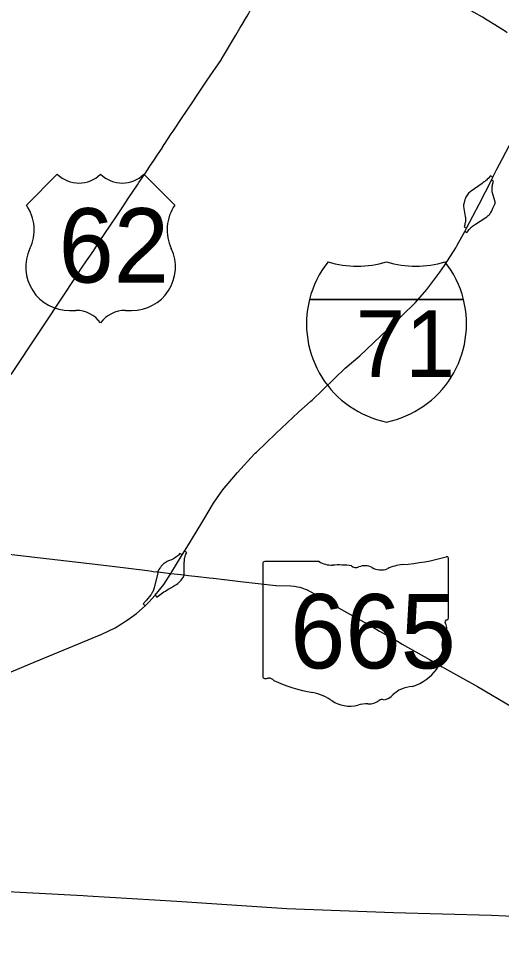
# Model space of a CAD drawing. Extents: x -7.1 to 34, y 0 to 22.
# Drawn here: x 4.231 to 5.069, y 14.423 to 16.034 of the extents above; entities that cross this region are included whole.
import ezdxf

# ---------------------------------------------------------------- set-up
doc = ezdxf.new("R2010")
doc.units = 0
for name, color, linetype in [('GM_X_County', 7, 'Continuous'), ('GM_X_Interchange_Ramps', 7, 'Continuous'), ('GM_X_Interstate_Route', 7, 'Continuous'), ('GM_X_Interstate_Shield', 7, 'Continuous'), ('GM_X_State_Route', 7, 'Continuous'), ('GM_X_State_Shield', 7, 'Continuous'), ('GM_X_US_Route', 7, 'Continuous'), ('GM_X_US_Shield', 7, 'Continuous')]:
    doc.layers.add(name, color=color, linetype=linetype)

msp = doc.modelspace()

# ---------------------------------------------------------------- linework, layer by layer
at = {"layer": 'GM_X_County'}
msp.add_lwpolyline([(6.4816, 14.3958), (6.2397, 14.409), (6.239, 14.4092), (5.9929, 14.4242), (5.7569, 14.4401), (5.6674, 14.444), (5.5093, 14.4541), (5.4881, 14.4554), (5.313, 14.4679), (5.276, 14.4703), (5.0902, 14.4781), (5.0763, 14.4786), (5.0514, 14.4796), (4.8814, 14.4845), (4.6962, 14.4912), (4.5056, 14.5037), (4.3509, 14.5133), (4.3432, 14.5137), (4.1028, 14.5264)], dxfattribs=at)
at = {"layer": 'GM_X_Interchange_Ramps'}
for points in [[(5.0539, 15.7589), (5.0496, 15.7612), (5.0454, 15.7566), (5.0441, 15.7553), (5.0426, 15.7538), (5.0415, 15.7528), (5.04, 15.7515), (5.0388, 15.7506), (5.0372, 15.7495), (5.035, 15.748), (5.0159, 15.7346), (5.0145, 15.7336), (5.0131, 15.7323), (5.0117, 15.7309), (5.0102, 15.7292), (5.009, 15.7276), (5.008, 15.7261), (5.007, 15.7244), (5.0061, 15.7227), (5.005, 15.7204), (5.0032, 15.7129), (5.003, 15.7108)], [(5.0576, 15.7139), (5.0575, 15.7158), (5.0528, 15.7336), (5.0526, 15.7354), (5.0525, 15.7372), (5.0524, 15.7389), (5.0525, 15.7407), (5.0526, 15.7426), (5.0529, 15.7444), (5.0532, 15.7462), (5.0536, 15.7481), (5.0548, 15.7521), (5.0513, 15.7539)], [(5.003, 15.7108), (5.0029, 15.7082), (5.0058, 15.6909), (5.0061, 15.6892), (5.0062, 15.6873), (5.0063, 15.6854), (5.0062, 15.6836), (5.006, 15.6816), (5.0058, 15.6799), (5.0054, 15.6784), (5.0049, 15.6765), (5.0037, 15.6726), (5.0081, 15.6702)], [(5.0052, 15.6648), (5.0085, 15.6631), (5.0128, 15.6682), (5.0138, 15.6693), (5.0147, 15.6703), (5.0158, 15.6714), (5.0169, 15.6723), (5.0186, 15.6737), (5.02, 15.6748), (5.0216, 15.676), (5.0237, 15.6773), (5.0399, 15.688), (5.0416, 15.6891), (5.0431, 15.6901), (5.0445, 15.6913), (5.0458, 15.6924), (5.0472, 15.6938), (5.0482, 15.695), (5.0493, 15.6964), (5.0503, 15.6978), (5.0512, 15.6992), (5.052, 15.7007), (5.0527, 15.7021), (5.0533, 15.7034), (5.0539, 15.7049), (5.0543, 15.706), (5.0547, 15.7073), (5.0571, 15.7122), (5.0576, 15.7139)], [(4.5184, 15.07), (4.5184, 15.0721), (4.5186, 15.0917), (4.5187, 15.0938), (4.5188, 15.0954), (4.519, 15.0968), (4.5192, 15.0985), (4.5195, 15.0998), (4.5199, 15.1012), (4.5203, 15.1026), (4.5208, 15.104), (4.5213, 15.1054), (4.5228, 15.1085), (4.5189, 15.1108)], [(4.5151, 15.1045), (4.5111, 15.1069), (4.5086, 15.1042), (4.5072, 15.1029), (4.5056, 15.1015), (4.5038, 15.1002), (4.5018, 15.0988), (4.5001, 15.0978), (4.4984, 15.0969), (4.4966, 15.0961), (4.4947, 15.0954), (4.4929, 15.0948), (4.4909, 15.094), (4.4891, 15.0932), (4.4871, 15.092), (4.4851, 15.0908), (4.4833, 15.0894), (4.4815, 15.0878), (4.4801, 15.0863), (4.4787, 15.0847), (4.4771, 15.0826), (4.476, 15.0813), (4.4746, 15.0792), (4.4733, 15.0769), (4.4727, 15.0748)], [(4.4727, 15.0748), (4.4726, 15.0734), (4.4664, 15.0471), (4.4659, 15.0455), (4.4654, 15.044), (4.4647, 15.0424), (4.4639, 15.0406), (4.4631, 15.0392), (4.4625, 15.0381), (4.4619, 15.0371), (4.4611, 15.036), (4.4604, 15.035), (4.4531, 15.0259), (4.4471, 15.0198), (4.4506, 15.0163)], [(4.468, 15.0344), (4.4712, 15.0313), (4.4737, 15.0332), (4.4759, 15.0349), (4.4785, 15.0368), (4.4808, 15.0385), (4.4832, 15.0401), (4.4858, 15.0418), (4.4889, 15.0438), (4.4916, 15.0455), (4.494, 15.0468), (4.4963, 15.0481), (4.5016, 15.0513), (4.5049, 15.0533), (4.5071, 15.0549), (4.5088, 15.0563), (4.5105, 15.0579), (4.5119, 15.0594), (4.5131, 15.0607), (4.5141, 15.0621), (4.5162, 15.0649), (4.5182, 15.0686), (4.5184, 15.07)]]:
    msp.add_lwpolyline(points, dxfattribs=at)
at = {"layer": 'GM_X_Interstate_Route'}
for points in [[(5.0439, 16.0309), (5.0356, 16.0359), (5.0066, 16.052), (4.9932, 16.0577), (4.9706, 16.0673), (4.9492, 16.0752), (4.9186, 16.0839), (4.8566, 16.1006), (4.8408, 16.1047), (4.7979, 16.1157), (4.773, 16.1221), (4.7497, 16.1282), (4.7392, 16.1309), (4.71, 16.1382), (4.6914, 16.1431)], [(5.0785, 16.0089), (5.0754, 16.011), (5.0574, 16.0229), (5.0439, 16.0309)], [(5.0609, 15.7724), (5.0655, 15.7812), (5.0815, 15.8118), (5.0979, 15.8401), (5.1079, 15.8562)], [(5.0551, 15.7611), (5.0609, 15.7724)], [(5.03, 15.7121), (5.03, 15.7121), (5.0513, 15.7539), (5.0539, 15.7589), (5.0551, 15.7611)], [(4.992, 15.6412), (5.0052, 15.6648), (5.0081, 15.6702), (5.03, 15.7121)], [(4.9315, 15.5555), (4.9392, 15.5644), (4.9619, 15.594), (4.97, 15.6056), (4.9893, 15.6366), (4.992, 15.6412)], [(4.8697, 15.4936), (4.88, 15.5032), (4.8971, 15.5195), (4.919, 15.541), (4.9315, 15.5555)], [(4.7382, 15.3705), (4.7401, 15.3722), (4.7977, 15.4277), (4.823, 15.4492), (4.859, 15.4835), (4.8697, 15.4936)], [(4.6404, 15.2792), (4.6415, 15.2804), (4.6435, 15.2826), (4.6776, 15.3146), (4.7168, 15.3516), (4.7382, 15.3705), (4.7382, 15.3705)], [(4.5524, 15.1659), (4.5692, 15.1939), (4.585, 15.2167), (4.611, 15.2473), (4.6404, 15.2792)], [(4.5227, 15.1172), (4.5488, 15.1599), (4.5524, 15.1659)], [(4.4954, 15.0722), (4.5151, 15.1045), (4.5189, 15.1108), (4.5227, 15.1172)], [(4.4273, 14.997), (4.4356, 15.0031), (4.4506, 15.0163), (4.4569, 15.0225), (4.468, 15.0344), (4.4829, 15.0533), (4.4954, 15.0722)], [(4.1211, 14.8623), (4.1234, 14.8633), (4.1817, 14.887), (4.2584, 14.9184), (4.3181, 14.9432), (4.3753, 14.9669), (4.3984, 14.9783), (4.4099, 14.985), (4.4149, 14.9883)], [(4.4149, 14.9883), (4.4214, 14.9926), (4.4273, 14.997)]]:
    msp.add_lwpolyline(points, dxfattribs=at)
at = {"layer": 'GM_X_Interstate_Shield'}
for p, q in [((4.7357, 15.5471), (5.0028, 15.5471)), ((5.0028, 15.5471), (4.7357, 15.5471)), ((5.0028, 15.5471), (4.7357, 15.5471))]:
    msp.add_line(p, q, dxfattribs=at)
for centre, start, end in [((4.904, 15.5046), 141.669, 165.8066), ((4.8186, 15.7781), 253.0091, 286.9909), ((4.92, 15.7781), 253.0091, 286.9909), ((4.8346, 15.5046), 14.1934, 38.331), ((4.904, 15.5046), 165.8066, 258.463), ((4.8346, 15.5046), 281.537, 14.1934)]:
    msp.add_arc(centre, 0.1735, start, end, dxfattribs=at)
at = {"layer": 'GM_X_State_Route'}
for points in [[(4.128, 15.1159), (4.1302, 15.1156), (4.2441, 15.1024), (4.269, 15.0995), (4.3292, 15.0924), (4.3936, 15.0847), (4.4548, 15.0771), (4.4622, 15.0762)], [(4.4622, 15.0762), (4.4646, 15.0759), (4.4707, 15.0751)], [(4.4707, 15.0751), (4.4727, 15.0748), (4.4954, 15.0722), (4.5184, 15.07), (4.526, 15.0688)], [(4.526, 15.0688), (4.5421, 15.067), (4.5428, 15.0669)], [(4.5428, 15.0669), (4.5619, 15.0646)], [(4.5619, 15.0646), (4.5689, 15.0638), (4.569, 15.0638)], [(4.569, 15.0638), (4.5871, 15.0619), (4.588, 15.0618), (4.5882, 15.0618)], [(4.5882, 15.0618), (4.6159, 15.0585), (4.6774, 15.0515), (4.6781, 15.0514), (4.7036, 15.0506), (4.7092, 15.0501), (4.7127, 15.0496)], [(4.7127, 15.0496), (4.7151, 15.0493), (4.7191, 15.0482), (4.7223, 15.0473), (4.7251, 15.0464), (4.7283, 15.0452), (4.7305, 15.0442), (4.7378, 15.0404)], [(4.7378, 15.0404), (4.7443, 15.037)], [(4.7443, 15.037), (4.7461, 15.036), (4.7862, 15.0129), (4.8447, 14.9799), (4.8574, 14.9721), (4.8881, 14.9549), (4.8964, 14.9499), (4.9437, 14.9231), (4.9656, 14.9107)], [(4.9656, 14.9107), (4.9696, 14.9084)], [(4.9696, 14.9084), (5.0216, 14.8791), (5.0268, 14.8764), (5.0878, 14.8403), (5.0908, 14.8386), (5.0937, 14.8377), (5.097, 14.8363), (5.1004, 14.8352), (5.1027, 14.8345), (5.1027, 14.8345)]]:
    msp.add_lwpolyline(points, dxfattribs=at)
at = {"layer": 'GM_X_State_Shield'}
for p, q in [((4.977, 14.9953), (4.977, 15.0977)), ((4.6549, 15.0894), (4.6549, 14.8939)), ((4.7524, 15.0928), (4.6581, 15.0928)), ((4.977, 14.9954), (4.977, 14.9953))]:
    msp.add_line(p, q, dxfattribs=at)
for centre, major_axis, start_param, end_param in [((4.8623, 15.3595), (0.3416, 0), 4.814394, 5.042369), ((4.9734, 15.0981), (0.00359, 0), 6.141152, 7.989035), ((4.6586, 15.0899), (0.00373, 0), 1.712693, 3.28349), ((4.7749, 15.1155), (0.0362, 0), 4.042523, 4.731795), ((4.7869, 14.983), (0.1299, 0), 1.404758, 1.657858), ((4.8164, 15.0909), (0.0104, 0), 3.836095, 5.185415), ((4.8317, 15.0683), (0.0217, 0), 0.950623, 2.079405), ((4.8597, 15.0993), (0.0261, 0), 4.081561, 5.145723), ((4.9059, 15.0331), (0.0687, 0), 1.699011, 2.107814), ((4.9762, 14.9878), (0.00555, 0), 1.883978, 3.671073), ((4.9409, 14.9749), (0.0333, 0), 5.934695, 6.695948), ((4.9732, 14.9949), (0.00384, 0), 5.05454, 6.418171), ((4.9899, 14.9525), (0.0242, 0), 2.387724, 3.262537), ((4.8814, 14.9395), (0.0854, 0), 5.101752, 6.440018), ((4.6586, 14.8934), (0.00376, 0), 3.00124, 4.508301), ((4.6592, 14.9134), (0.0287, 0), 4.665946, 4.897461), ((4.6651, 14.8826), (0.0104, 0), 0.519207, 1.627899), ((4.7959, 15.0583), (0.2467, 0), 4.195997, 4.488961), ((4.9174, 14.8389), (0.0468, 0), 1.647645, 2.488434), ((4.7223, 14.806), (0.0772, 0), 0.823519, 1.323587), ((4.8613, 14.848), (0.00735, 0), 1.147584, 2.315152), ((4.8582, 14.8749), (0.0276, 0), 4.937069, 5.64225), ((4.8058, 14.8816), (0.049, 0), 4.026481, 4.996735), ((4.8341, 14.814), (0.0402, 0), 1.495662, 1.94098), ((4.8377, 14.867), (0.0261, 0), 4.691044, 5.507374)]:
    msp.add_ellipse(centre, major_axis=major_axis, ratio=0.8, start_param=start_param, end_param=end_param, dxfattribs=at)
at = {"layer": 'GM_X_US_Route'}
for points in [[(4.541, 15.901), (4.5581, 15.9267), (4.5584, 15.9271), (4.5828, 15.9627), (4.5832, 15.9634), (4.6077, 16.0047), (4.615, 16.0169), (4.6216, 16.028), (4.6219, 16.0285), (4.6292, 16.0409), (4.6323, 16.0462), (4.6363, 16.0529), (4.6429, 16.0642), (4.6436, 16.0652), (4.6515, 16.077), (4.6611, 16.0912)], [(4.5355, 15.8929), (4.5399, 15.8994), (4.541, 15.901)], [(4.496, 15.8339), (4.4992, 15.8385), (4.5163, 15.8642), (4.5211, 15.8714), (4.5345, 15.8913), (4.5355, 15.8929)], [(4.48, 15.8093), (4.4802, 15.8095), (4.4838, 15.8156), (4.4842, 15.8162), (4.4959, 15.8337), (4.496, 15.8339)], [(4.4527, 15.7682), (4.4554, 15.7722), (4.459, 15.7776), (4.4656, 15.7876), (4.4698, 15.7939), (4.4733, 15.7991), (4.48, 15.8093)], [(4.4015, 15.692), (4.4106, 15.7055), (4.4224, 15.7234), (4.43, 15.7348), (4.4375, 15.7458), (4.4399, 15.7495), (4.4522, 15.7674), (4.4527, 15.7682)], [(4.3669, 15.6403), (4.3712, 15.647), (4.3907, 15.6759), (4.4015, 15.692)], [(4.3491, 15.6138), (4.3614, 15.632), (4.3669, 15.6403)], [(4.2185, 15.4169), (4.314, 15.5614), (4.3415, 15.603), (4.3479, 15.6121), (4.3491, 15.6138)]]:
    msp.add_lwpolyline(points, dxfattribs=at)
at = {"layer": 'GM_X_US_Shield'}
for p, q in [((4.2983, 15.7641), (4.2446, 15.7104)), ((4.5023, 15.7104), (4.4486, 15.7641)), ((4.3198, 15.5279), (4.3305, 15.5279)), ((4.4164, 15.5279), (4.4271, 15.5279))]:
    msp.add_line(p, q, dxfattribs=at)
for centre, radius, start, end in [((4.3359, 15.8024), 0.0537, 225.573, 314.427), ((4.411, 15.8024), 0.0537, 225.573, 314.427), ((4.183, 15.6673), 0.0752, 334.5471, 35.0009), ((4.5639, 15.6673), 0.0752, 144.9991, 205.4529), ((4.3189, 15.603), 0.0752, 154.8319, 270.6383), ((4.428, 15.603), 0.0752, 269.3617, 25.1681), ((4.3305, 15.4742), 0.0537, 36.8699, 90), ((4.4164, 15.4742), 0.0537, 90, 143.1301)]:
    msp.add_arc(centre, radius, start, end, dxfattribs=at)

# ---------------------------------------------------------------- texts
at = {"layer": 'GM_X_Interstate_Shield'}
msp.add_text('71', height=0.11569, dxfattribs=at).set_placement((4.8158, 15.4126))
at = {"layer": 'GM_X_State_Shield'}
msp.add_text('665', height=0.12885, dxfattribs=at).set_placement((4.7021, 14.9077))
at = {"layer": 'GM_X_US_Shield'}
msp.add_text('62', height=0.12885, dxfattribs=at).set_placement((4.3005, 15.5762))

doc.saveas('drawing.dxf')
